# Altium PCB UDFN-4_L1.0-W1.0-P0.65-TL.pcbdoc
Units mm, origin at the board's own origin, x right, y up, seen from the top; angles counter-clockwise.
Board outline 14.1 x 13.91 mm, 2 copper layers (Top Layer, Bottom Layer), stack 0 mm thick; 1 components, 0 nets, 5 pads, 0 vias.
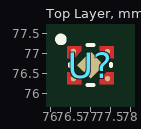
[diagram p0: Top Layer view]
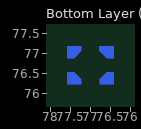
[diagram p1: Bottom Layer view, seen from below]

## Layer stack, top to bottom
Top Layer: signal copper (thickness not stored)
Bottom Layer: signal copper (thickness not stored)

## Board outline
83.946,69.85 69.85,69.85 69.85,83.76 83.946,83.76

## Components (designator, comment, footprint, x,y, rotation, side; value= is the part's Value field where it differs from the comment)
U? "" UDFN-4_L1.0-W1.0-P0.65-TL 77.01,76.7 r0 top

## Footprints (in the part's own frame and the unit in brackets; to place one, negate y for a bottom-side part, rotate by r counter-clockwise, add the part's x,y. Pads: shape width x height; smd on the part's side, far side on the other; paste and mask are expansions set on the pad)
UDFN-4_L1.0-W1.0-P0.65-TL [mm]
  round 0.132 smd: 1(-0.427,0.341) 2(-0.427,-0.34) 3(0.427,-0.341) 4(0.427,0.34)
  rect 0.48x0.48 smd rot 135: 5(0.002,0.001)
  Top Layer region: -0.226,-0.474 -0.586,-0.474 -0.586,-0.174 -0.406,-0.174 -0.226,-0.354
  Top Layer region: -0.226,0.476 -0.586,0.476 -0.586,0.176 -0.406,0.176 -0.226,0.356
  Top Layer region: 0.226,0.475 0.586,0.475 0.586,0.175 0.406,0.175 0.226,0.355
  Top Layer region: 0.226,-0.476 0.586,-0.476 0.586,-0.175 0.406,-0.175 0.226,-0.355
  Bottom Layer region: -0.226,-0.474 -0.586,-0.474 -0.586,-0.174 -0.406,-0.174 -0.226,-0.354
  Bottom Layer region: -0.226,0.476 -0.586,0.476 -0.586,0.176 -0.406,0.176 -0.226,0.356
  Bottom Layer region: 0.226,0.475 0.586,0.475 0.586,0.175 0.406,0.175 0.226,0.355
  Bottom Layer region: 0.226,-0.476 0.586,-0.476 0.586,-0.175 0.406,-0.175 0.226,-0.355
  Multi-Layer region: -0.226,-0.474 -0.586,-0.474 -0.586,-0.174 -0.406,-0.174 -0.226,-0.354
  Multi-Layer region: -0.226,0.476 -0.586,0.476 -0.586,0.176 -0.406,0.176 -0.226,0.356
  Multi-Layer region: 0.226,0.475 0.586,0.475 0.586,0.175 0.406,0.175 0.226,0.355
  Multi-Layer region: 0.226,-0.476 0.586,-0.476 0.586,-0.175 0.406,-0.175 0.226,-0.355
  silkscreen extent -0.81,-0.5 0.51,0.71

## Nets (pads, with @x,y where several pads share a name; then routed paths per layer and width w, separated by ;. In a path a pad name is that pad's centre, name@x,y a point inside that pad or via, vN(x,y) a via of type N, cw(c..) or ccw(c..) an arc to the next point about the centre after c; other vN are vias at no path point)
pads on no net: U?.1 U?.2 U?.3 U?.4 U?.5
